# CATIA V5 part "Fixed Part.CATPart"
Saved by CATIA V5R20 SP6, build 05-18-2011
Part number: Fixed Part
Bounding box of the stored display mesh (mm): x -700 to 700, y -240 to 240, z 0 to 1074.99
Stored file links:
  E:\#01 CATIA Lecture Materials\#06 DMU\#01 DMU KIN Page01 EX01\#01 CATPart\Fixed Part.CATPart
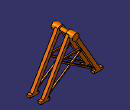
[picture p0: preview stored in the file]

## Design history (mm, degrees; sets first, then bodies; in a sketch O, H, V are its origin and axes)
Body1 (main body)
Body2
  Body3
    Sketch1 on zx-plane, origin (0, 0, 0), H (-1, 0, 0), V (0, 0, 1)
      circle A1 centre (0, 1000) radius 75
    Pad1: profile Sketch1, direction (0, -1, 0), length 240, opposite side length -120
  Assemble1: tool Body3
  Body4
    Sketch2 on zx-plane, origin (0, 0, 0), H (-1, 0, 0), V (0, 0, 1)
      arc A1 centre (0, 1000) radius 75 from (-37.5, 935.0481) to (37.5, 935.0481) ccw
      line L1 (-64.9519, 1037.5) -> (-635.0853, 50)
      line L2 (-37.5, 935.0481) -> (-548.4828, 50)
      line L3 (-635.0853, 50) -> (-700, 50)
      line L4 (-700, 0) -> (-700, 50)
      line L5 (-500, 0) -> (-700, 0)
      line L6 (-500, 0) -> (-500, 50)
      line L7 (-500, 50) -> (-548.4828, 50)
      line L8 (37.5, 935.0481) -> (548.4828, 50)
      line L9 (64.9519, 1037.5) -> (635.0853, 50)
      line L10 (500, 50) -> (548.4828, 50)
      line L11 (500, 0) -> (500, 50)
      line L12 (500, 0) -> (700, 0)
      line L13 (700, 0) -> (700, 50)
      line L14 (635.0853, 50) -> (700, 50)
      arc A2 centre (0, 1000) radius 75 from (64.9519, 1037.5) to (-64.9519, 1037.5) ccw
      coincidence: A1 A2
    Pad2: profile Sketch2, direction (0, -1, 0), length 160, opposite side length -90
    Body5
      Sketch3 on zx-plane, origin (0, 0, 0), H (-1, 0, 0), V (0, 0, 1)
        line L1 (-230.9358, 600.0074) -> (0, 445.9487)
        line L2 (230.9358, 600.0074) -> (0, 445.9487)
        line L3 (243.462, 578.3114) -> (22.5244, 430.9225)
        line L4 (-243.462, 578.3114) -> (-22.5244, 430.9225)
        line L5 (-22.5244, 430.9225) -> (-520.2631, 98.8779)
        line L6 (0, 415.8963) -> (-548.4828, 50)
        line L7 (-230.9358, 600.0074) -> (-243.462, 578.3114)
        line L8 (230.9358, 600.0074) -> (243.462, 578.3114)
        line L9 (-520.2631, 98.8779) -> (-548.4828, 50)
        point P13 (-520.2631, 98.8779)
        line L10 (520.2631, 98.8779) -> (548.4828, 50)
        line L11 (22.5244, 430.9225) -> (520.2631, 98.8779)
        line L12 (0, 415.8963) -> (548.4828, 50)
        coincidence: P13 L7, P13 L5, L1 L11, L4 L12
        parallelism: L9 L7, L10 L8
      Pad3: profile Sketch3, direction (0, -1, 0), length 140, opposite side length -110
      Sketch4 on zx-plane, origin (0, 0, 0), H (-1, 0, 0), V (0, 0, 1)
        line L1 (216.5064, 625) -> (-216.5064, 625)
        line L2 (230.9401, 600) -> (-230.9401, 600)
        line L3 (-216.5064, 625) -> (-230.9401, 600)
        line L4 (216.5064, 625) -> (230.9401, 600)
      Pad4: profile Sketch4, direction (0, -1, 0), length 140, opposite side length -110
    Assemble2: tool Body5
  Assemble3: tool Body4
  Mirror1: of the body so far, about zx-plane
  Body6
    Sketch5 on zx-plane, origin (0, 0, 0), H (-1, 0, 0), V (0, 0, 1)
      circle A1 centre (0, 1000) radius 40
    Pad5: profile Sketch5, direction (0, 1, 0), length 240, opposite side length 240
  Assemble4: tool Body6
